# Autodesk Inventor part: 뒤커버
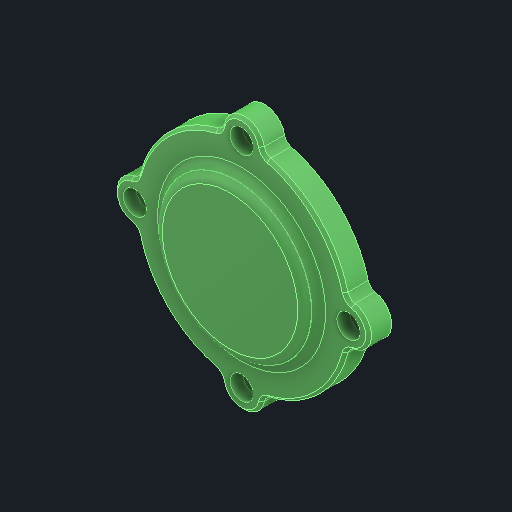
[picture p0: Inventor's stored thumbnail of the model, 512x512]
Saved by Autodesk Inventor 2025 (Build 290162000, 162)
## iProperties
Created: 2025-08
Part Number: 뒤커버
Material: 알루미늄 6061
Document SubType Name: Modeling
Designer: infra023
Density: 2.71 g/cm^3
Appearance: 기본값
Company: 한국ATC센터
Author: jhkim
Sending System: Autodesk Inventor 2026
Preprocessor: ST-DEVELOPER v20.1
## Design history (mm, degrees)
feature "솔리드1"
node "솔리드2"
